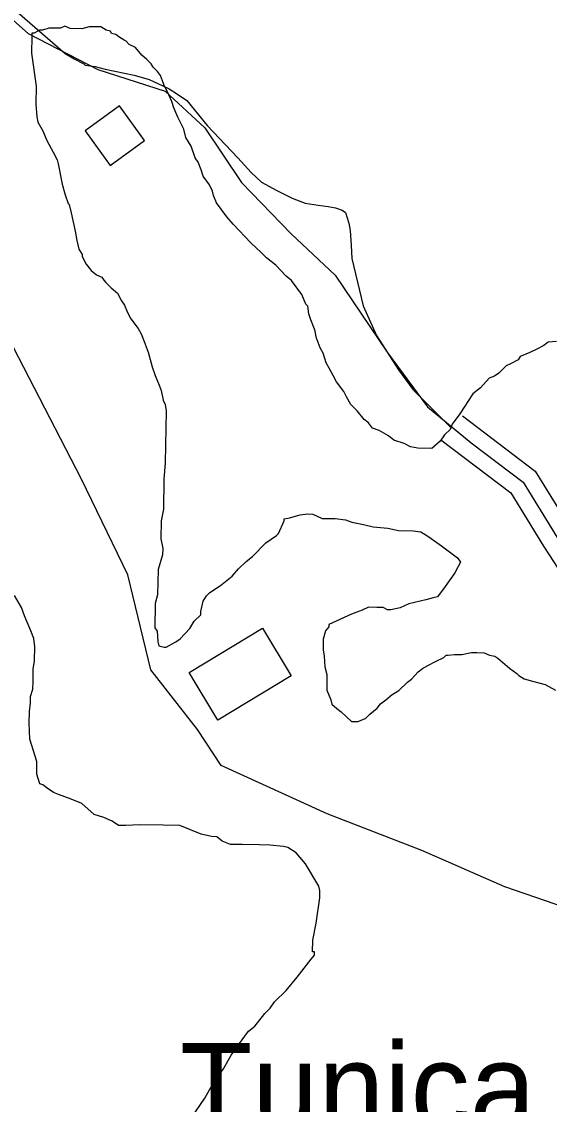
# Model space of a CAD drawing. Extents: x 3192986 to 3230865, y 867483 to 892886.
# Drawn here: x 3215434 to 3215927, y 885140 to 886154 of the extents above; entities that cross this region are included whole.
import ezdxf

# ---------------------------------------------------------------- set-up
doc = ezdxf.new("R2010")
doc.units = 0
for name, color, linetype in [('V-BLDG-OTLN', 7, 'Continuous'), ('V-ROAD-CNTR', 7, 'Continuous'), ('V-SITE-OTLN-IDEN', 7, 'Continuous'), ('V-SITE-VEGE', 7, 'Continuous'), ('V-TOPO-SHOR', 7, 'Continuous')]:
    doc.layers.add(name, color=color, linetype=linetype)

msp = doc.modelspace()

# ---------------------------------------------------------------- linework, layer by layer
at = {"layer": 'V-BLDG-OTLN'}
for points in [[(3215516.3, 886019.3), (3215548.7, 886042.8), (3215525.2, 886075.2), (3215492.9, 886051.7)], [(3215590.3, 885544.4), (3215658.9, 885585.9), (3215685.9, 885541.3), (3215617.3, 885499.8)]]:
    msp.add_lwpolyline(points, close=True, dxfattribs=at)
at = {"layer": 'V-ROAD-CNTR'}
for points in [[(3215392.6, 886184.8), (3215439.8, 886143), (3215504.8, 886109), (3215567.9, 886088.9), (3215605, 886054.4), (3215639.3, 886003.2), (3215685.9, 885955.3), (3215727, 885916.6), (3215775.7, 885844.4), (3215813.4, 885793.4), (3215854.4, 885759.6), (3215902.9, 885722.8), (3215934.8, 885670.9), (3216002.1, 885567.3), (3216062.5, 885481.5), (3216122.2, 885390.4), (3216163.7, 885319.1), (3216217, 885256.5), (3216266.3, 885207.9), (3216311.6, 885174.7), (3216338.4, 885153.4)], [(3215429.3, 886163.1), (3215474.4, 886124.2), (3215482.9, 886119), (3215491.9, 886114.3), (3215493.2, 886113.3), (3215502.3, 886111.9), (3215511.8, 886109.6), (3215539, 886103.8), (3215552.9, 886099.7), (3215565.6, 886093.9), (3215571.6, 886090.9), (3215579.6, 886086), (3215588.1, 886080), (3215607.3, 886056.7), (3215636, 886026.5), (3215648.5, 886012.7), (3215658, 886003.7), (3215672.4, 885995.8), (3215686.8, 885988.7), (3215699.1, 885983.9), (3215711.2, 885982), (3215720.4, 885980.8), (3215727.3, 885979.7), (3215733.7, 885977.4), (3215736.6, 885975.4), (3215739.8, 885965.4), (3215741.1, 885958.5), (3215742, 885944.5), (3215742.6, 885932.3), (3215753.3, 885887.7), (3215765.8, 885860), (3215786.4, 885827.8), (3215800.1, 885809.1), (3215835.9, 885773.4)], [(3215846.2, 885784.7), (3215914.2, 885733.1), (3215947.5, 885678.9), (3216014.5, 885575.7), (3216074.9, 885490), (3216134.9, 885398.3), (3216176, 885327.8), (3216228, 885266.7), (3216276, 885219.3), (3216320.7, 885186.6), (3216347.7, 885165.2)], [(3215825.9, 885762.4), (3215891.6, 885712.6), (3215922.1, 885662.9), (3215989.6, 885558.8), (3216050.1, 885473.1), (3216109.4, 885382.5), (3216151.4, 885310.4), (3216206, 885246.3), (3216256.5, 885196.4), (3216302.5, 885162.8), (3216329, 885141.7)]]:
    msp.add_lwpolyline(points, dxfattribs=at)
msp.add_spline([(3215149.6, 889400.3), (3215155.9, 889267.8), (3215168.9, 889195.4), (3215160.6, 889137.3), (3215154.9, 889075.6), (3215164.4, 888991.1), (3215195.1, 888909.8), (3215210, 888842.2), (3215221.9, 888778.6), (3215221.6, 888687.8), (3215213.7, 888610.2), (3215209.9, 888580.9), (3215198.1, 888544), (3215180.6, 888492.6), (3215151.8, 888427.6), (3215144.7, 888383.9), (3215149.4, 888332.4), (3215179.5, 888265.9), (3215221.5, 888194.5), (3215247.7, 888146.7), (3215251.6, 888102.8), (3215251.4, 888061.4), (3215258.1, 888025.7), (3215272.7, 887982.1), (3215304.4, 887912.4), (3215338.5, 887846.4), (3215378, 887784.3), (3215410.9, 887728.3), (3215457.2, 887682.3), (3215490.5, 887647.9), (3215526.4, 887629.4), (3215571.3, 887624.1), (3215625, 887619.9), (3215699.1, 887611.6), (3215741.3, 887603.5), (3215785, 887581.7), (3215832.7, 887564), (3215882.5, 887543.1), (3215927.8, 887516.9), (3215982.7, 887460.3), (3216039.8, 887360.7), (3216082.9, 887294.2), (3216125.1, 887215.1), (3216163.7, 887141.7), (3216182, 887053.4), (3216206.3, 886963.2), (3216237.9, 886871.5), (3216258.9, 886828.6), (3216274.2, 886747.9), (3216285.4, 886688.1), (3216291.4, 886622.7), (3216286, 886531.6), (3216272.6, 886432.4), (3216265.5, 886374.2), (3216269.8, 886313.9), (3216279.2, 886242.5), (3216289.8, 886193.6), (3216315.9, 886099.5), (3216339.7, 886009.2), (3216363.6, 885942.8), (3216392.5, 885866.7), (3216411.5, 885800.1), (3216419.9, 885741.4), (3216427.6, 885690.9), (3216440.2, 885654.1), (3216470.9, 885622.4), (3216485.4, 885609.9), (3216409.2, 885579)], degree=3, dxfattribs=at)
at = {"layer": 'V-SITE-VEGE'}
for p, q in [((3215459.1, 886147.9), (3215453.2, 886146)), ((3215470.1, 886147.7), (3215459.1, 886147.9)), ((3215474.1, 886149.6), (3215470.1, 886147.7)), ((3215479, 886147.5), (3215474.1, 886149.6)), ((3215496.9, 886149.2), (3215489.9, 886147.3)), ((3215507.8, 886149), (3215496.9, 886149.2)), ((3215512.7, 886145.9), (3215507.8, 886149)), ((3215443.1, 886140.2), (3215442.9, 886124.4)), ((3215443.2, 886143.2), (3215443.1, 886140.2)), ((3215445.2, 886143.2), (3215443.2, 886143.2)), ((3215450.2, 886146.1), (3215445.2, 886143.2)), ((3215453.2, 886146), (3215450.2, 886146.1)), ((3215489.9, 886147.3), (3215479, 886147.5)), ((3215516.7, 886144.9), (3215512.7, 886145.9)), ((3215517.6, 886142.9), (3215516.7, 886144.9)), ((3215521.6, 886141.8), (3215517.6, 886142.9)), ((3215524.5, 886139.8), (3215521.6, 886141.8)), ((3215529.4, 886136.7), (3215524.5, 886139.8)), ((3215531.4, 886135.7), (3215529.4, 886136.7)), ((3215534.3, 886132.7), (3215531.4, 886135.7)), ((3215540.2, 886129.6), (3215534.3, 886132.7)), ((3215546, 886122.5), (3215540.2, 886129.6)), ((3215442.9, 886124.4), (3215447.3, 886093.5)), ((3215550.9, 886118.5), (3215546, 886122.5)), ((3215554.8, 886114.4), (3215550.9, 886118.5)), ((3215556.8, 886111.4), (3215554.8, 886114.4)), ((3215560.7, 886107.4), (3215556.8, 886111.4)), ((3215563.6, 886103.4), (3215560.7, 886107.4)), ((3215567.4, 886093.4), (3215563.6, 886103.4)), ((3215447.3, 886093.5), (3215447, 886076.7)), ((3215570.2, 886088.3), (3215567.4, 886093.4)), ((3215574.1, 886079.3), (3215570.2, 886088.3)), ((3215575.9, 886073.4), (3215574.1, 886079.3)), ((3215447, 886076.7), (3215447.7, 886064.7)), ((3215579.7, 886064.4), (3215575.9, 886073.4)), ((3215447.7, 886064.7), (3215448.6, 886059.7)), ((3215448.6, 886059.7), (3215453.5, 886051.7)), ((3215585.5, 886053.3), (3215579.7, 886064.4)), ((3215453.5, 886051.7), (3215457.3, 886042.7)), ((3215587.3, 886045.4), (3215585.5, 886053.3)), ((3215457.3, 886042.7), (3215463, 886031.7)), ((3215592.2, 886037.3), (3215587.3, 886045.4)), ((3215595.9, 886026.4), (3215592.2, 886037.3)), ((3215463, 886031.7), (3215466.9, 886024.7)), ((3215598.8, 886022.3), (3215595.9, 886026.4)), ((3215466.9, 886024.7), (3215467.8, 886020.7)), ((3215467.8, 886020.7), (3215471.4, 886001.8)), ((3215601.7, 886015.3), (3215598.8, 886022.3)), ((3215603.6, 886009.3), (3215601.7, 886015.3)), ((3215609.4, 886001.3), (3215603.6, 886009.3)), ((3215471.4, 886001.8), (3215474.2, 885991.8)), ((3215612.3, 885995.3), (3215609.4, 886001.3)), ((3215474.2, 885991.8), (3215477.1, 885983.8)), ((3215613.2, 885991.3), (3215612.3, 885995.3)), ((3215616, 885984.3), (3215613.2, 885991.3)), ((3215477.1, 885983.8), (3215478, 885982.8)), ((3215478, 885982.8), (3215479.9, 885974.8)), ((3215625.7, 885971.2), (3215616, 885984.3)), ((3215479.9, 885974.8), (3215483.6, 885957.9)), ((3215631.5, 885964.2), (3215625.7, 885971.2)), ((3215483.6, 885957.9), (3215485.4, 885948.9)), ((3215648.1, 885947), (3215631.5, 885964.2)), ((3215485.4, 885948.9), (3215487.2, 885941)), ((3215657.9, 885937.9), (3215648.1, 885947)), ((3215487.2, 885941), (3215490.1, 885935.9)), ((3215490.1, 885935.9), (3215490.1, 885934)), ((3215662.8, 885932.9), (3215657.9, 885937.9)), ((3215490.1, 885934), (3215493.9, 885926.9)), ((3215493.9, 885926.9), (3215498.8, 885920.9)), ((3215671.6, 885925.8), (3215662.8, 885932.9)), ((3215681.3, 885915.7), (3215671.6, 885925.8)), ((3215498.8, 885920.9), (3215503.7, 885916.8)), ((3215503.7, 885916.8), (3215508.6, 885914.8)), ((3215508.6, 885914.8), (3215510.5, 885911.8)), ((3215686.2, 885911.6), (3215681.3, 885915.7)), ((3215510.5, 885911.8), (3215512.5, 885909.7)), ((3215512.5, 885909.7), (3215517.3, 885904.7)), ((3215517.3, 885904.7), (3215523.2, 885899.6)), ((3215695.9, 885898.5), (3215686.2, 885911.6)), ((3215523.2, 885899.6), (3215527.1, 885892.6)), ((3215699.7, 885889.5), (3215695.9, 885898.5)), ((3215527.1, 885892.6), (3215530, 885888.6)), ((3215530, 885888.6), (3215532.8, 885881.6)), ((3215701.6, 885887.5), (3215699.7, 885889.5)), ((3215702.5, 885880.5), (3215701.6, 885887.5)), ((3215532.8, 885881.6), (3215535.7, 885875.6)), ((3215535.7, 885875.6), (3215542.5, 885866.5)), ((3215704.4, 885874.6), (3215702.5, 885880.5)), ((3215708.2, 885864.6), (3215704.4, 885874.6)), ((3215542.5, 885866.5), (3215545.4, 885861.5)), ((3215709.1, 885858.6), (3215708.2, 885864.6)), ((3215545.4, 885861.5), (3215548.2, 885854.5)), ((3215548.2, 885854.5), (3215552, 885844.5)), ((3215712.9, 885848.6), (3215709.1, 885858.6)), ((3215926.3, 885853.7), (3215922.3, 885850.8)), ((3215934.3, 885854.6), (3215926.3, 885853.7)), ((3215552, 885844.5), (3215555.7, 885830.6)), ((3215715.8, 885843.6), (3215712.9, 885848.6)), ((3215718.6, 885834.6), (3215715.8, 885843.6)), ((3215909.3, 885844.1), (3215900.3, 885840.3)), ((3215915.3, 885847), (3215909.3, 885844.1)), ((3215922.3, 885850.8), (3215915.3, 885847)), ((3215721.5, 885829.6), (3215718.6, 885834.6)), ((3215891.2, 885833.5), (3215887.2, 885831.6)), ((3215898.3, 885837.4), (3215891.2, 885833.5)), ((3215900.3, 885840.3), (3215898.3, 885837.4)), ((3215555.7, 885830.6), (3215558.6, 885822.6)), ((3215725.3, 885822.6), (3215721.5, 885829.6)), ((3215880.2, 885824.8), (3215876.1, 885821.9)), ((3215887.2, 885831.6), (3215880.2, 885824.8)), ((3215558.6, 885822.6), (3215562.4, 885813.6)), ((3215562.4, 885813.6), (3215564.3, 885808.6)), ((3215728.2, 885816.6), (3215725.3, 885822.6)), ((3215735, 885807.5), (3215728.2, 885816.6)), ((3215871.2, 885820), (3215863.1, 885811.2)), ((3215876.1, 885821.9), (3215871.2, 885820)), ((3215564.3, 885808.6), (3215566.1, 885799.6)), ((3215737.8, 885802.5), (3215735, 885807.5)), ((3215856, 885805.4), (3215843.8, 885786.7)), ((3215863.1, 885811.2), (3215856, 885805.4)), ((3215566.1, 885799.6), (3215568, 885795.6)), ((3215568, 885795.6), (3215568.9, 885789.6)), ((3215741.7, 885795.5), (3215737.8, 885802.5)), ((3215747.5, 885789.4), (3215741.7, 885795.5)), ((3215568.9, 885789.6), (3215568, 885741)), ((3215754.3, 885781.4), (3215747.5, 885789.4)), ((3215843.8, 885786.7), (3215836.6, 885776.9)), ((3215758.3, 885778.3), (3215754.3, 885781.4)), ((3215762.1, 885773.3), (3215758.3, 885778.3)), ((3215768.1, 885771.2), (3215762.1, 885773.3)), ((3215836.6, 885776.9), (3215834.6, 885772)), ((3215776.9, 885766.1), (3215768.1, 885771.2)), ((3215781.8, 885762), (3215776.9, 885766.1)), ((3215829.5, 885767.1), (3215825.4, 885761.2)), ((3215834.6, 885772), (3215829.5, 885767.1)), ((3215791.7, 885758.9), (3215781.8, 885762)), ((3215797.6, 885755.8), (3215791.7, 885758.9)), ((3215804.5, 885754.7), (3215797.6, 885755.8)), ((3215817.4, 885754.4), (3215804.5, 885754.7)), ((3215825.4, 885761.2), (3215817.4, 885754.4)), ((3215568, 885741), (3215566.8, 885725.2)), ((3215566.8, 885725.2), (3215566.3, 885697.4)), ((3215566.3, 885697.4), (3215564.1, 885686.5)), ((3215684.2, 885689.3), (3215694.2, 885692.1)), ((3215694.2, 885692.1), (3215701.2, 885693)), ((3215701.2, 885693), (3215706.1, 885692.9)), ((3215706.1, 885692.9), (3215715, 885688.8)), ((3215564.1, 885686.5), (3215563.8, 885669.6)), ((3215674, 885674.6), (3215679.2, 885686.4)), ((3215679.2, 885688.4), (3215684.2, 885689.3)), ((3215679.2, 885686.4), (3215679.2, 885688.4)), ((3215715, 885688.8), (3215726.9, 885688.6)), ((3215726.9, 885688.6), (3215736.8, 885687.4)), ((3215736.8, 885687.4), (3215742.7, 885685.3)), ((3215742.7, 885685.3), (3215753.6, 885683.1)), ((3215753.6, 885683.1), (3215762.5, 885681)), ((3215662, 885665.9), (3215672, 885672.7)), ((3215672, 885672.7), (3215674, 885674.6)), ((3215762.5, 885681), (3215776.4, 885679.7)), ((3215776.4, 885679.7), (3215786.2, 885677.6)), ((3215786.2, 885677.6), (3215800.1, 885677.3)), ((3215800.1, 885677.3), (3215807.1, 885676.2)), ((3215807.1, 885676.2), (3215813.9, 885672.1)), ((3215813.9, 885672.1), (3215816.9, 885670.1)), ((3215563.8, 885669.6), (3215565.6, 885660.7)), ((3215649.8, 885653.2), (3215662, 885665.9)), ((3215816.9, 885670.1), (3215826.7, 885663)), ((3215826.7, 885663), (3215841.4, 885651.8)), ((3215565.5, 885654.7), (3215561.3, 885640.9)), ((3215565.6, 885660.7), (3215565.5, 885654.7)), ((3215643.8, 885648.4), (3215649.8, 885653.2)), ((3215841.4, 885651.8), (3215844.3, 885647.8)), ((3215561.3, 885640.9), (3215560.9, 885617.1)), ((3215630.6, 885634.7), (3215636.7, 885641.5)), ((3215636.7, 885641.5), (3215643.8, 885648.4)), ((3215844.3, 885647.8), (3215839.1, 885637.9)), ((3215619.6, 885626), (3215630.6, 885634.7)), ((3215839.1, 885637.9), (3215830, 885625.2)), ((3215609.5, 885619.2), (3215615.5, 885623.1)), ((3215615.5, 885623.1), (3215619.6, 885626)), ((3215830, 885625.2), (3215822.8, 885615.4)), ((3215433.6, 885605.5), (3215426.9, 885616.5)), ((3215560.9, 885617.1), (3215558.7, 885609.2)), ((3215601.3, 885601.5), (3215603.4, 885611.4)), ((3215603.4, 885611.4), (3215606.5, 885616.3)), ((3215606.5, 885616.3), (3215609.5, 885619.2)), ((3215811.9, 885612.6), (3215795.9, 885608.9)), ((3215818.9, 885614.5), (3215811.9, 885612.6)), ((3215822.8, 885615.4), (3215818.9, 885614.5)), ((3215436.4, 885597.5), (3215433.6, 885605.5)), ((3215558.7, 885609.2), (3215558.3, 885586.4)), ((3215601.2, 885598.5), (3215601.3, 885601.5)), ((3215752.2, 885602.8), (3215742.2, 885599)), ((3215758.2, 885605.6), (3215752.2, 885602.8)), ((3215766.1, 885605.5), (3215758.2, 885605.6)), ((3215772.1, 885605.4), (3215766.1, 885605.5)), ((3215776, 885603.3), (3215772.1, 885605.4)), ((3215779, 885603.3), (3215776, 885603.3)), ((3215787.9, 885605.1), (3215779, 885603.3)), ((3215795.9, 885608.9), (3215787.9, 885605.1)), ((3215442.1, 885583.5), (3215436.4, 885597.5)), ((3215591.1, 885585.8), (3215595.2, 885592.6)), ((3215595.2, 885592.6), (3215601.2, 885598.5)), ((3215742.2, 885599), (3215721.1, 885589.4)), ((3215445, 885576.5), (3215442.1, 885583.5)), ((3215558.3, 885586.4), (3215560.3, 885583.3)), ((3215560.3, 885583.3), (3215561.1, 885573.4)), ((3215582, 885576), (3215591.1, 885585.8)), ((3215718.1, 885583.5), (3215715.9, 885575.6)), ((3215721.1, 885587.4), (3215718.1, 885583.5)), ((3215721.1, 885589.4), (3215721.1, 885587.4)), ((3215445.9, 885568.5), (3215445, 885576.5)), ((3215561.1, 885573.4), (3215562, 885569.4)), ((3215568.9, 885568.3), (3215577.9, 885573.1)), ((3215577.9, 885573.1), (3215582, 885576)), ((3215715.9, 885575.6), (3215715.8, 885565.7)), ((3215445.6, 885555.6), (3215445.9, 885568.5)), ((3215562, 885569.4), (3215566.9, 885568.3)), ((3215566.9, 885568.3), (3215568.9, 885568.3)), ((3215715.8, 885565.7), (3215716.6, 885559.7)), ((3215716.6, 885559.7), (3215717.5, 885549.8)), ((3215828.8, 885558.7), (3215830.8, 885560.7)), ((3215830.8, 885560.7), (3215832.8, 885560.6)), ((3215832.8, 885560.6), (3215838.8, 885561.5)), ((3215838.8, 885561.5), (3215841.7, 885561.5)), ((3215841.7, 885561.5), (3215845.7, 885561.4)), ((3215845.7, 885561.4), (3215854.7, 885563.2)), ((3215854.7, 885563.2), (3215859.6, 885563.1)), ((3215859.6, 885563.1), (3215866.6, 885563)), ((3215866.6, 885563), (3215871.5, 885560.9)), ((3215871.5, 885560.9), (3215876.4, 885559.8)), ((3215876.4, 885559.8), (3215879.4, 885557.8)), ((3215444.5, 885547.7), (3215445.6, 885555.6)), ((3215717.5, 885549.8), (3215719.3, 885542.8)), ((3215808.7, 885548.2), (3215813.8, 885551)), ((3215813.8, 885551), (3215820.8, 885554.9)), ((3215820.8, 885554.9), (3215828.8, 885558.7)), ((3215879.4, 885557.8), (3215890.1, 885548.7)), ((3215444.3, 885535.8), (3215444.5, 885547.7)), ((3215719.3, 885542.8), (3215719.1, 885527.9)), ((3215798.6, 885538.4), (3215804.7, 885545.2)), ((3215804.7, 885545.2), (3215808.7, 885548.2)), ((3215890.1, 885548.7), (3215897, 885543.6)), ((3215897, 885543.6), (3215898.9, 885541.6)), ((3215898.9, 885541.6), (3215903.9, 885538.5)), ((3215444.2, 885528.8), (3215444.3, 885535.8)), ((3215786.5, 885527.7), (3215794.6, 885535.5)), ((3215794.6, 885535.5), (3215798.6, 885538.4)), ((3215903.9, 885538.5), (3215911.8, 885536.4)), ((3215911.8, 885536.4), (3215923.6, 885533.2)), ((3215923.6, 885533.2), (3215933.4, 885528.1)), ((3215441.9, 885516), (3215442, 885521.9)), ((3215442, 885521.9), (3215444.2, 885528.8)), ((3215719.1, 885527.9), (3215722.9, 885518.9)), ((3215774.5, 885519), (3215780.5, 885523.8)), ((3215780.5, 885523.8), (3215786.5, 885527.7)), ((3215440.8, 885508.1), (3215441.9, 885516)), ((3215722.9, 885518.9), (3215723.8, 885514.9)), ((3215723.8, 885514.9), (3215728.7, 885510.9)), ((3215728.7, 885510.9), (3215732.6, 885507.8)), ((3215759.4, 885505.4), (3215766.4, 885511.2)), ((3215766.4, 885511.2), (3215769.4, 885515.1)), ((3215769.4, 885515.1), (3215774.5, 885519)), ((3215440.6, 885497.1), (3215440.8, 885508.1)), ((3215732.6, 885507.8), (3215742.4, 885498.7)), ((3215748.3, 885498.6), (3215755.3, 885501.5)), ((3215755.3, 885501.5), (3215759.4, 885505.4)), ((3215441.3, 885482.2), (3215440.6, 885497.1)), ((3215742.4, 885498.7), (3215748.3, 885498.6)), ((3215447.9, 885461.3), (3215441.3, 885482.2)), ((3215447.7, 885449.4), (3215447.9, 885461.3)), ((3215450.5, 885440.4), (3215447.7, 885449.4)), ((3215453.5, 885439.3), (3215450.5, 885440.4)), ((3215457.4, 885436.3), (3215453.5, 885439.3)), ((3215463.3, 885432.2), (3215457.4, 885436.3)), ((3215468.2, 885430.2), (3215463.3, 885432.2)), ((3215480, 885426), (3215468.2, 885430.2)), ((3215489.9, 885421.8), (3215480, 885426)), ((3215501.6, 885411.7), (3215489.9, 885421.8)), ((3215510.5, 885408.6), (3215501.6, 885411.7)), ((3215518.4, 885405.4), (3215510.5, 885408.6)), ((3215524.3, 885401.4), (3215518.4, 885405.4)), ((3215531.2, 885401.2), (3215524.3, 885401.4)), ((3215544.1, 885402), (3215531.2, 885401.2)), ((3215566, 885401.6), (3215544.1, 885402)), ((3215581.8, 885401.3), (3215566, 885401.6)), ((3215601.5, 885393), (3215581.8, 885401.3)), ((3215611.4, 885390.9), (3215601.5, 885393)), ((3215616.4, 885390.8), (3215611.4, 885390.9)), ((3215621.3, 885386.7), (3215616.4, 885390.8)), ((3215629.1, 885383.6), (3215621.3, 885386.7)), ((3215640.1, 885383.4), (3215629.1, 885383.6)), ((3215655.9, 885383.1), (3215640.1, 885383.4)), ((3215665.9, 885383), (3215655.9, 885383.1)), ((3215678.7, 885381.7), (3215665.9, 885383)), ((3215682.7, 885380.7), (3215678.7, 885381.7)), ((3215690.5, 885375.6), (3215682.7, 885380.7)), ((3215699.3, 885365.5), (3215690.5, 885375.6)), ((3215711.8, 885344.4), (3215699.3, 885365.5)), ((3215712.7, 885340.4), (3215711.8, 885344.4)), ((3215712.6, 885333.5), (3215712.7, 885340.4)), ((3215709.2, 885309.7), (3215712.6, 885333.5)), ((3215706, 885293.9), (3215709.2, 885309.7)), ((3215705.8, 885283), (3215706, 885293.9)), ((3215691.5, 885259.4), (3215704.7, 885276.1)), ((3215704.7, 885276.1), (3215707.7, 885280)), ((3215707.7, 885283), (3215705.8, 885283)), ((3215707.7, 885280), (3215707.7, 885283)), ((3215681.3, 885246.7), (3215691.5, 885259.4)), ((3215670.2, 885236), (3215681.3, 885246.7)), ((3215666.1, 885230.1), (3215670.2, 885236)), ((3215659, 885222.3), (3215661.1, 885225.2)), ((3215661.1, 885225.2), (3215666.1, 885230.1)), ((3215651.9, 885213.5), (3215659, 885222.3)), ((3215636.7, 885195.9), (3215645.9, 885208.6)), ((3215645.9, 885208.6), (3215651.9, 885213.5)), ((3215629.6, 885186.1), (3215636.7, 885195.9)), ((3215622.4, 885173.3), (3215629.6, 885186.1)), ((3215612.2, 885158.6), (3215622.4, 885173.3)), ((3215605.1, 885145.8), (3215612.2, 885158.6)), ((3215592.8, 885128.2), (3215605.1, 885145.8))]:
    msp.add_line(p, q, dxfattribs=at)
at = {"layer": 'V-TOPO-SHOR'}
msp.add_lwpolyline([(3216238.3, 885062.7), (3216150.6, 885174.7), (3216095.6, 885230.7), (3215952.1, 885321), (3215885.7, 885343.9), (3215808.2, 885377.9), (3215719.7, 885412.1), (3215620.2, 885457.5), (3215598.3, 885491.1), (3215554.4, 885547), (3215533.1, 885636.1), (3215489.5, 885725.4), (3215391.4, 885915.2), (3215369.5, 885948.7), (3215072, 886196), (3214929, 886330.7), (3214863, 886397.9), (3214819.4, 886487.2), (3214764.8, 886576.6)], dxfattribs=at)

# ---------------------------------------------------------------- texts
at = {"layer": 'V-SITE-OTLN-IDEN'}
msp.add_text('Tunica      ', height=83, dxfattribs=at).set_placement((3215581.8, 885114.5))

doc.saveas('drawing.dxf')
